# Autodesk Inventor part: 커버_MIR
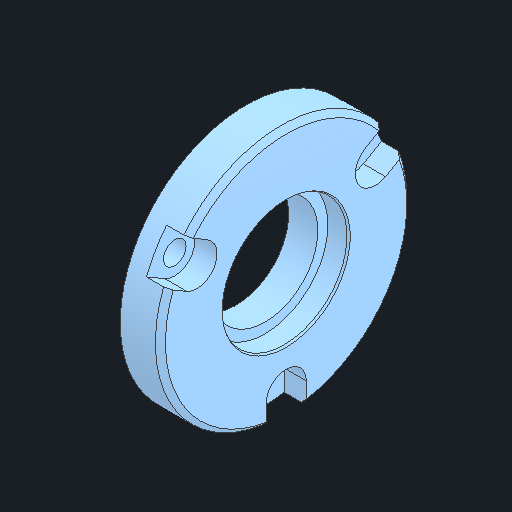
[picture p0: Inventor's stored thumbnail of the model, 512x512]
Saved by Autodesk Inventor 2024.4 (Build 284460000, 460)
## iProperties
Created: 2025-10
Part Number: 커버_MIR
Material: 알루미늄 6061
Document SubType Name: Modeling
Designer: user
Density: 2.7 g/cm^3
Appearance: 기본값
Author: jhkim
Sending System: Autodesk Inventor 2026
Preprocessor: ST-DEVELOPER v20.1
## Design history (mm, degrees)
derived "커버.ipt"
feature "솔리드2::커버.ipt" dims "d0" = 10
tag "피쳐 태그1"
node "솔리드2"
